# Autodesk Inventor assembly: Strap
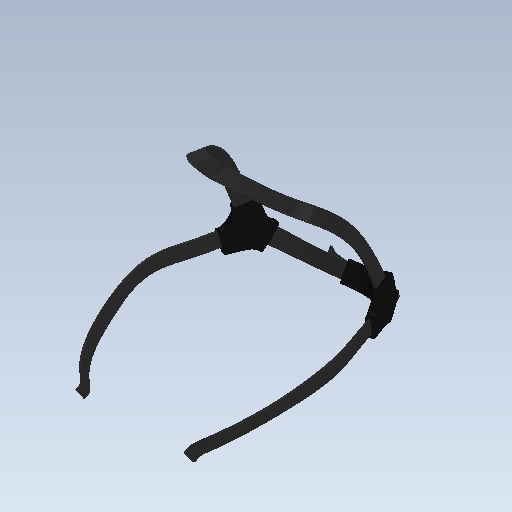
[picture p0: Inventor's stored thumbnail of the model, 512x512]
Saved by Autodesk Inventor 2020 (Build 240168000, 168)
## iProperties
Created: 2021-10
Part Number: Strap
Document SubType Name: Assembly
Designer: bruno
Author: bruno
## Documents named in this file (5)
- C:\Users\bruno\Downloads\ember-diamond-bike-helmet-1.snapshot.1\Strap.iam
- C:\Users\bruno\Downloads\ember-diamond-bike-helmet-1.snapshot.1\strap clips.ipt
- C:\Users\bruno\Downloads\ember-diamond-bike-helmet-1.snapshot.1\Strap 15mm.ipt
- C:\Users\bruno\Downloads\ember-diamond-bike-helmet-1.snapshot.1\Buckle.ipt
- C:\Users\bruno\Downloads\ember-diamond-bike-helmet-1.snapshot.1\Pièce12.ipt
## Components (4 placed, 4 different names)
1. strap clips:1
2. Strap 15mm:1
3. Buckle:1
4. Pièce12
